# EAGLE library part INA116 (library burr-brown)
Instrumentation Amplifier Ultra Low Input Bias Current
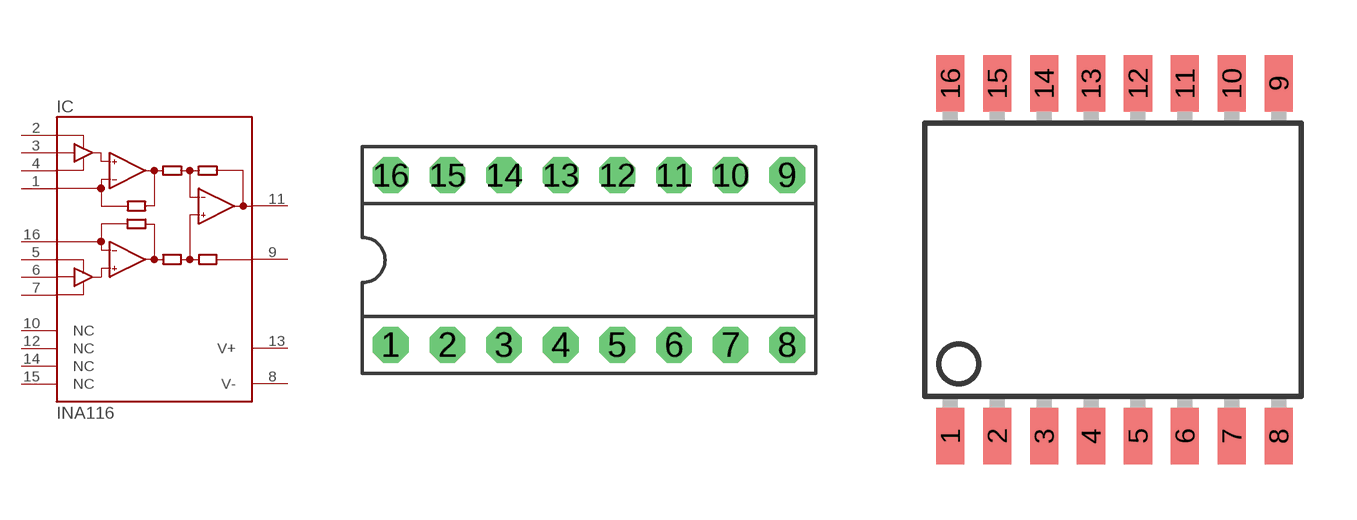
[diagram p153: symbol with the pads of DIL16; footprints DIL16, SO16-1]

Designator prefix IC

## INA116P (MF: TEXAS INSTRUMENT CONNECTORS; MPN: INA116PA; OC_FARNELL: 1231983; OC_NEWARK: 78K8300)  [DIL16]
1  RG  pas
2  GUARD-  pas
3  -IN  in
4  GUARD-  pas
5  GUARD+  pas
6  +IN  in
7  GUARD+  pas
8  V-  pwr
9  REF  pas
10  NC  nc
11  OUT  out
12  NC  nc
13  V+  pwr
14  NC  nc
15  NC  nc
16  RG  pas

## INA116U (MF: TEXAS INSTRUMENTS; MPN: INA116UA; OC_FARNELL: 1212402; OC_NEWARK: 35C1717)  [SO16-1]
Pads as for DIL16

## Footprint DIL16 (pad centres in mm)
Dual In Line
drill 0.813 pad 1.6 octagon: 1 -8.89,-3.81; 2 -6.35,-3.81; 3 -3.81,-3.81; 4 -1.27,-3.81; 5 1.27,-3.81; 6 3.81,-3.81; 7 6.35,-3.81; 8 8.89,-3.81; 9 8.89,3.81; 10 6.35,3.81; 11 3.81,3.81; 12 1.27,3.81; 13 -1.27,3.81; 14 -3.81,3.81; 15 -6.35,3.81; 16 -8.89,3.81

## Footprint SO16-1 (pad centres in mm)
Small Outline Package
smd 0.762 x 1.524: 1 -4.445,-4.775; 2 -3.175,-4.775; 3 -1.905,-4.775; 4 -0.635,-4.775; 5 0.635,-4.775; 6 1.905,-4.775; 7 3.175,-4.775; 8 4.445,-4.775; 9 4.445,4.775; 10 3.175,4.775; 11 1.905,4.775; 12 0.635,4.775; 13 -0.635,4.775; 14 -1.905,4.775; 15 -3.175,4.775; 16 -4.445,4.775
